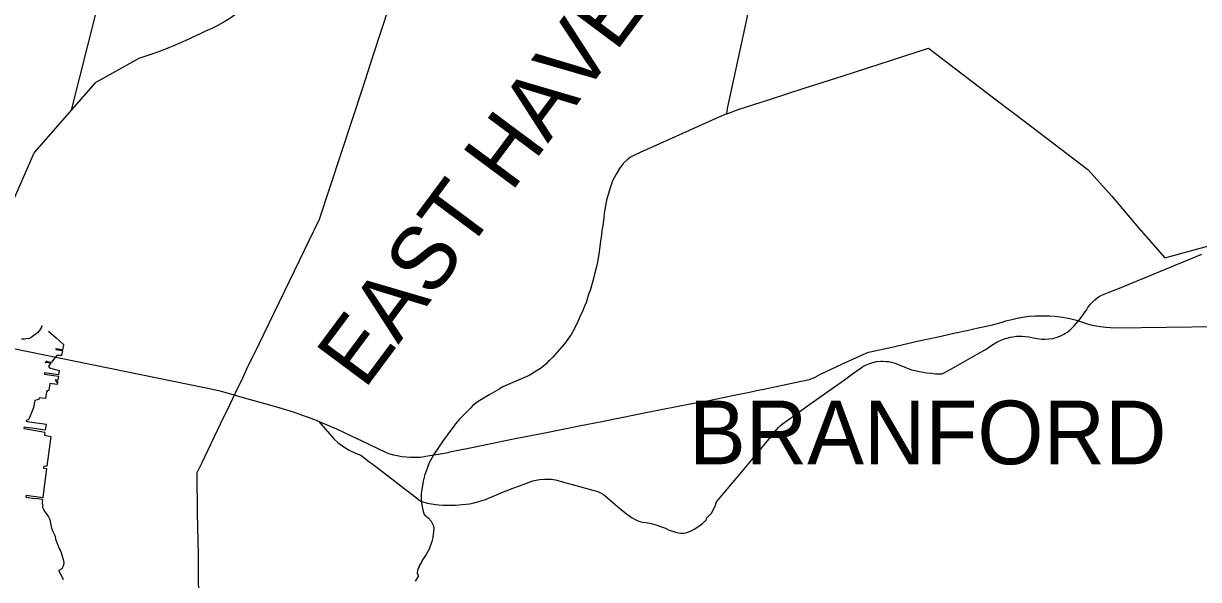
# Model space of a CAD drawing. Extents: x 0 to 2603, y -226 to 830.
# Drawn here: x 163.93 to 188.86, y 524.55 to 536.34 of the extents above; entities that cross this region are included whole.
import ezdxf

# ---------------------------------------------------------------- set-up
doc = ezdxf.new("R2010")
doc.units = 0
for name, color, linetype in [('CT_TSH_Map_Interstate_Roads', 7, 'Continuous'), ('CT_TSH_Map_Town_Limits', 7, 'Continuous'), ('CT_TSH_Map_Town_Text', 7, 'Continuous'), ('CT_TSH_Map_US_and_State_Routes', 7, 'Continuous')]:
    doc.layers.add(name, color=color, linetype=linetype)

msp = doc.modelspace()

# ---------------------------------------------------------------- linework, layer by layer
at = {"layer": 'CT_TSH_Map_Interstate_Roads'}
for p, q in [((167.427, 536.006), (167.102, 535.864)), ((167.496, 536.038), (167.427, 536.006)), ((167.664, 536.117), (167.496, 536.038)), ((167.102, 535.864), (167.029, 535.837))]:
    msp.add_line(p, q, dxfattribs=at)
for points in [[(168.438, 536.542), (168.306, 536.451), (168.203, 536.383), (168.043, 536.292), (167.925, 536.239)], [(167.925, 536.239), (167.791, 536.179), (167.664, 536.117)], [(167.029, 535.837), (166.836, 535.759), (166.589, 535.669), (166.375, 535.601), (165.455, 535.085), (164.16, 533.608), (162.631, 530.136), (162.528, 530.129)], [(184.259, 529.902), (184.487, 529.953), (184.596, 529.976), (184.693, 530.007), (184.769, 530.031), (184.898, 530.066), (185.01, 530.092), (185.13, 530.112)], [(185.13, 530.112), (185.257, 530.13), (185.395, 530.14)], [(185.395, 530.14), (185.581, 530.144), (185.701, 530.139), (185.818, 530.13), (185.972, 530.111)], [(185.972, 530.111), (186.13, 530.082), (186.241, 530.054)], [(186.241, 530.054), (186.312, 530.033)], [(186.312, 530.033), (186.527, 529.962)], [(162.328, 529.732), (167.774, 528.618), (167.942, 528.583), (168.096, 528.546)], [(182.35, 529.478), (182.926, 529.608), (183.333, 529.696), (183.667, 529.772), (183.943, 529.832)], [(183.943, 529.832), (184.187, 529.886)], [(184.187, 529.886), (184.259, 529.902)], [(186.527, 529.962), (186.575, 529.951)], [(186.575, 529.951), (186.688, 529.93), (186.782, 529.915), (186.892, 529.902), (186.991, 529.894), (187.111, 529.889)], [(187.111, 529.889), (189.25, 529.915)], [(180.668, 528.815), (180.73, 528.842), (180.823, 528.896), (180.934, 528.947), (181.309, 529.119), (181.604, 529.256), (181.76, 529.327), (181.822, 529.355), (181.855, 529.367), (181.892, 529.376), (182.35, 529.478)], [(179.971, 528.657), (180.433, 528.751)], [(180.433, 528.751), (180.511, 528.767), (180.565, 528.78), (180.608, 528.793), (180.668, 528.815)], [(168.096, 528.546), (168.227, 528.512)], [(168.227, 528.512), (168.664, 528.386)], [(178.469, 528.346), (179.044, 528.465), (179.334, 528.522)], [(179.334, 528.522), (179.554, 528.57)], [(179.554, 528.57), (179.605, 528.579)], [(179.605, 528.579), (179.635, 528.587), (179.971, 528.657)], [(168.664, 528.386), (169.098, 528.263), (169.418, 528.172), (169.652, 528.103), (169.843, 528.036), (169.968, 527.991), (170.141, 527.924)], [(176.963, 528.053), (177.206, 528.103), (178.075, 528.273), (178.469, 528.346)], [(176.234, 527.907), (176.963, 528.053)], [(170.141, 527.924), (170.219, 527.89)], [(170.219, 527.89), (170.351, 527.838)], [(170.351, 527.838), (170.571, 527.743), (170.866, 527.604)], [(174.328, 527.528), (174.992, 527.66), (175.718, 527.805), (176.234, 527.907)], [(170.866, 527.604), (171.111, 527.487)], [(171.111, 527.487), (171.627, 527.239)], [(172.974, 527.252), (173.083, 527.273), (173.475, 527.353), (174.328, 527.528)], [(171.627, 527.239), (171.705, 527.213), (171.784, 527.19), (171.858, 527.174)], [(172.469, 527.161), (172.941, 527.244)], [(172.941, 527.244), (172.974, 527.252)], [(171.858, 527.174), (171.961, 527.158), (172.047, 527.146), (172.14, 527.141), (172.231, 527.139)], [(172.231, 527.139), (172.352, 527.144), (172.469, 527.161)]]:
    msp.add_lwpolyline(points, dxfattribs=at)
at = {"layer": 'CT_TSH_Map_Town_Limits'}
for points in [[(178.85, 534.429), (178.87, 534.538), (179.241, 536.265), (179.978, 539.735), (179.975, 541.521), (179.973, 543.992), (179.973, 545.11)], [(167.652, 523.762), (167.642, 525.074), (167.623, 525.943), (167.614, 526.813), (167.724, 527.029), (168.112, 527.846), (168.302, 528.237), (168.496, 528.653), (168.567, 528.79), (168.701, 529.078), (168.81, 529.297), (168.822, 529.327), (169.785, 531.317), (169.895, 531.537), (169.99, 531.738), (170.213, 532.193), (171.133, 534.977), (171.359, 535.685), (172.331, 538.662)], [(178.85, 534.429), (179.115, 534.528), (179.734, 534.723), (180.515, 534.975), (181.302, 535.228), (182.105, 535.49), (183.129, 535.818), (184.513, 534.768), (185.204, 534.24), (186.513, 533.249), (187.012, 532.685), (187.596, 531.998), (188.147, 531.37), (189.079, 531.624), (190.687, 532.071), (191.755, 532.367), (192.004, 532.439), (192.634, 532.598)], [(178.845, 534.426), (178.608, 534.324), (177.078, 533.636), (177.03, 533.611), (176.891, 533.549), (176.81, 533.506), (176.736, 533.452), (176.656, 533.372), (176.579, 533.268), (176.504, 533.148), (176.43, 533.004), (176.375, 532.859), (176.3, 532.592), (176.25, 532.317), (176.24, 532.221), (176.219, 532.057), (176.206, 531.988), (176.203, 531.943), (176.192, 531.866), (176.189, 531.82), (176.176, 531.726), (176.135, 531.449), (176.126, 531.372), (176.106, 531.279), (176.084, 531.159), (176.046, 531.023), (176.018, 530.901), (175.953, 530.68), (175.923, 530.616), (175.909, 530.575), (175.866, 530.419), (175.842, 530.366), (175.807, 530.265), (175.73, 530.105), (175.702, 530.033), (175.615, 529.858), (175.552, 529.746), (175.412, 529.548), (175.206, 529.31), (175.158, 529.264), (175.094, 529.194), (175.064, 529.17), (175.015, 529.114), (174.977, 529.086), (174.92, 529.038), (174.66, 528.873), (174.409, 528.765), (174.098, 528.634), (174.022, 528.582), (173.823, 528.472), (173.577, 528.324), (173.519, 528.281), (173.466, 528.236), (173.411, 528.181), (173.314, 528.081), (173.181, 527.945), (173.096, 527.848), (173.027, 527.751), (172.994, 527.715), (172.818, 527.476), (172.649, 527.222), (172.546, 527.033), (172.519, 526.964), (172.494, 526.898), (172.472, 526.848), (172.446, 526.774), (172.41, 526.63), (172.374, 526.415), (172.37, 526.372), (172.37, 526.259), (172.383, 526.126), (172.407, 525.992), (172.424, 525.936), (172.446, 525.911), (172.518, 525.853), (172.577, 525.786), (172.623, 525.698), (172.639, 525.636), (172.631, 525.56), (172.62, 525.505), (172.614, 525.435), (172.596, 525.35), (172.539, 525.191), (172.476, 525.079), (172.381, 524.941), (172.381, 524.93), (172.321, 524.821), (172.323, 524.816), (172.305, 524.781), (172.29, 524.735), (172.285, 524.675), (172.288, 524.661), (172.303, 524.641), (172.303, 524.612), (172.243, 524.511)], [(164.323, 529.938), (164.316, 529.897), (164.274, 529.83), (164.23, 529.782), (164.119, 529.702)], [(164.462, 529.816), (164.627, 529.674)], [(164.119, 529.702), (164.087, 529.674), (164.051, 529.659), (164.034, 529.656), (164.019, 529.663), (163.952, 529.646), (163.886, 529.644)], [(164.627, 529.674), (164.783, 529.531)], [(164.777, 529.518), (164.757, 529.42)], [(164.783, 529.531), (164.777, 529.518)], [(164.595, 529.248), (164.522, 529.156)], [(164.756, 529.405), (164.739, 529.298), (164.635, 529.3), (164.595, 529.248)], [(164.757, 529.42), (164.617, 529.438), (164.616, 529.426), (164.756, 529.405)], [(164.509, 529.138), (164.413, 529.153), (164.401, 529.144), (164.392, 529.15), (164.423, 529.187), (164.436, 529.171), (164.522, 529.156)], [(164.509, 529.138), (164.472, 529.089), (164.468, 529.058), (164.481, 529.037), (164.503, 529.027), (164.689, 528.984), (164.675, 528.889)], [(164.675, 528.889), (164.38, 528.929), (164.376, 528.905), (164.671, 528.862)], [(164.657, 528.772), (164.609, 528.78), (164.605, 528.765), (164.655, 528.756)], [(164.654, 528.745), (164.626, 528.75), (164.623, 528.737), (164.65, 528.732)], [(164.655, 528.756), (164.654, 528.745)], [(164.671, 528.862), (164.657, 528.772)], [(164.65, 528.732), (164.642, 528.684), (164.487, 528.704), (164.468, 528.555), (164.436, 528.548), (164.421, 528.528), (164.396, 528.389), (164.263, 528.403)], [(164.263, 528.403), (164.253, 528.363), (164.168, 528.345), (164.143, 528.195), (164.135, 528.173)], [(164.135, 528.173), (164.042, 527.95)], [(164.062, 527.72), (163.944, 527.743), (163.949, 527.782), (164.062, 527.766)], [(164.042, 527.95), (164.033, 527.934), (163.989, 527.921), (163.989, 527.908), (164.01, 527.899), (164.41, 527.841), (164.393, 527.718)], [(164.393, 527.718), (164.062, 527.766)], [(164.386, 527.664), (164.062, 527.72)], [(164.379, 527.618), (164.377, 527.607), (164.509, 527.577), (164.426, 526.949)], [(164.386, 527.664), (164.379, 527.618)], [(164.418, 526.894), (164.361, 526.461)], [(164.418, 526.894), (164.363, 526.904), (164.373, 526.956), (164.426, 526.949)], [(164.341, 526.282), (163.99, 526.328), (163.984, 526.293), (164.169, 526.265)], [(164.337, 526.243), (164.169, 526.265)], [(164.337, 526.243), (164.328, 526.188)], [(164.361, 526.461), (164.341, 526.282)], [(164.328, 526.188), (164.327, 526.158)], [(164.327, 526.158), (164.339, 526.128), (164.334, 526.101), (164.334, 526.075), (164.346, 526.044)], [(164.346, 526.044), (164.383, 525.98), (164.389, 525.972)], [(164.389, 525.972), (164.46, 525.873)], [(164.46, 525.873), (164.487, 525.819), (164.503, 525.74), (164.525, 525.638), (164.552, 525.567), (164.601, 525.464), (164.61, 525.404), (164.69, 525.207), (164.702, 525.179)], [(164.702, 525.179), (164.729, 525.12), (164.772, 524.973), (164.784, 524.909), (164.782, 524.851), (164.761, 524.797), (164.742, 524.775), (164.684, 524.739), (164.68, 524.72), (164.738, 524.621), (164.772, 524.547)]]:
    msp.add_lwpolyline(points, dxfattribs=at)
at = {"layer": 'CT_TSH_Map_US_and_State_Routes'}
for points in [[(164.946, 534.505), (166.172, 539.356), (166.653, 541.86), (169.173, 545.726), (172.168, 553.089), (180.318, 573.415), (180.169, 577.311)], [(187.268, 530.76), (188.931, 531.45)], [(186.932, 530.628), (186.967, 530.641), (187.251, 530.754), (187.268, 530.76)], [(186.624, 530.447), (186.663, 530.482), (186.704, 530.515), (186.755, 530.549), (186.795, 530.572), (186.857, 530.601)], [(186.857, 530.601), (186.932, 530.628)], [(186.45, 530.217), (186.484, 530.264), (186.514, 530.315)], [(186.514, 530.315), (186.557, 530.374), (186.58, 530.402), (186.624, 530.447)], [(186.223, 529.927), (186.312, 530.033)], [(186.312, 530.033), (186.327, 530.046), (186.406, 530.153)], [(186.406, 530.153), (186.45, 530.217)], [(185.532, 529.643), (185.596, 529.643), (185.683, 529.649), (185.772, 529.663), (185.86, 529.687), (185.954, 529.725), (186.004, 529.752), (186.039, 529.771), (186.084, 529.8), (186.135, 529.841), (186.166, 529.869), (186.211, 529.912)], [(186.211, 529.912), (186.223, 529.927)], [(184.166, 529.33), (184.369, 529.443), (184.405, 529.466), (184.455, 529.503), (184.51, 529.541), (184.605, 529.596), (184.635, 529.611), (184.671, 529.625)], [(184.671, 529.625), (184.721, 529.643)], [(184.721, 529.643), (184.766, 529.658)], [(184.766, 529.658), (184.801, 529.67), (184.861, 529.686), (184.921, 529.697), (184.996, 529.706), (185.049, 529.709), (185.119, 529.71)], [(185.119, 529.71), (185.179, 529.705), (185.261, 529.698), (185.396, 529.665), (185.435, 529.659), (185.532, 529.643)], [(183.607, 529.01), (183.868, 529.16), (184.166, 529.33)], [(180.828, 528.418), (181.347, 528.785), (181.516, 528.909), (181.703, 529.04), (181.739, 529.062), (181.797, 529.094), (181.83, 529.11), (181.865, 529.124), (181.947, 529.151), (182.026, 529.168), (182.117, 529.178), (182.165, 529.18), (182.233, 529.173)], [(182.233, 529.173), (182.292, 529.168), (182.344, 529.157), (182.403, 529.141), (182.628, 529.05), (182.773, 528.997), (182.879, 528.972), (182.978, 528.95), (183.094, 528.932), (183.194, 528.921), (183.283, 528.913), (183.412, 528.912)], [(183.412, 528.912), (183.453, 528.925), (183.607, 529.01)], [(180.271, 528.022), (180.617, 528.267), (180.828, 528.418)], [(179.784, 527.572), (179.857, 527.663), (179.949, 527.773), (179.985, 527.809), (180.037, 527.849), (180.271, 528.022)], [(170.19, 527.903), (170.475, 527.579)], [(170.475, 527.579), (170.522, 527.525), (170.602, 527.451), (170.653, 527.409), (170.746, 527.345), (170.843, 527.289), (170.974, 527.227)], [(179.415, 527.13), (179.784, 527.572)], [(170.974, 527.227), (171.085, 527.181), (171.26, 527.049)], [(171.26, 527.049), (171.318, 527.004)], [(171.318, 527.004), (171.53, 526.843)], [(179.134, 526.791), (179.415, 527.13)], [(171.53, 526.843), (171.749, 526.679)], [(178.637, 526.191), (179.134, 526.791)], [(171.749, 526.679), (171.938, 526.533)], [(171.938, 526.533), (172.036, 526.459), (172.078, 526.424)], [(174.274, 526.468), (174.585, 526.585), (174.739, 526.638)], [(174.739, 526.638), (174.806, 526.652), (174.879, 526.666), (174.991, 526.674)], [(174.991, 526.674), (175.135, 526.672)], [(175.135, 526.672), (175.217, 526.658), (175.264, 526.649), (175.344, 526.626)], [(175.344, 526.626), (175.39, 526.612)], [(175.39, 526.612), (175.496, 526.581)], [(175.496, 526.581), (175.6, 526.554)], [(175.6, 526.554), (175.853, 526.483)], [(172.078, 526.424), (172.338, 526.224), (172.361, 526.21), (172.372, 526.204)], [(173.392, 526.154), (173.494, 526.172), (173.613, 526.205), (173.732, 526.246)], [(173.732, 526.246), (174.118, 526.405), (174.225, 526.447)], [(174.225, 526.447), (174.274, 526.468)], [(175.853, 526.483), (176.008, 526.44)], [(176.008, 526.44), (176.113, 526.41)], [(176.113, 526.41), (176.189, 526.377), (176.233, 526.352), (176.275, 526.323), (176.371, 526.235), (176.482, 526.139)], [(172.372, 526.204), (172.425, 526.188), (172.505, 526.167), (172.585, 526.149)], [(172.585, 526.149), (172.636, 526.141), (172.681, 526.135), (172.74, 526.129)], [(172.74, 526.129), (172.828, 526.124)], [(172.828, 526.124), (172.892, 526.121), (172.985, 526.123), (173.094, 526.126), (173.243, 526.138), (173.392, 526.154)], [(176.482, 526.139), (176.611, 526.031), (176.726, 525.936), (176.795, 525.887), (176.845, 525.853), (176.892, 525.825), (176.95, 525.8)], [(178.527, 525.954), (178.604, 526.105)], [(178.604, 526.105), (178.637, 526.191)], [(176.95, 525.8), (177.005, 525.779), (177.06, 525.764), (177.131, 525.754), (177.244, 525.732), (177.343, 525.709), (177.469, 525.666)], [(178.259, 525.678), (178.333, 525.735), (178.387, 525.781), (178.406, 525.796), (178.417, 525.82), (178.423, 525.835), (178.425, 525.856)], [(178.425, 525.856), (178.527, 525.954)], [(177.469, 525.666), (177.552, 525.632), (177.631, 525.595), (177.653, 525.588)], [(177.653, 525.588), (177.728, 525.564), (177.784, 525.544), (177.825, 525.534), (177.874, 525.529), (177.935, 525.529), (177.983, 525.537)], [(177.983, 525.537), (178.026, 525.55), (178.084, 525.574), (178.176, 525.623)], [(178.176, 525.623), (178.204, 525.641)], [(178.204, 525.641), (178.239, 525.664)], [(178.239, 525.664), (178.259, 525.678)]]:
    msp.add_lwpolyline(points, dxfattribs=at)

# ---------------------------------------------------------------- texts
at = {"layer": 'CT_TSH_Map_Town_Text'}
msp.add_text('EAST HAVEN', height=1.35, rotation=53.3505, dxfattribs=at).set_placement((171.162, 528.557))
msp.add_text('BRANFORD', height=1.35, dxfattribs=at).set_placement((178.05, 526.991))

doc.saveas('drawing.dxf')
